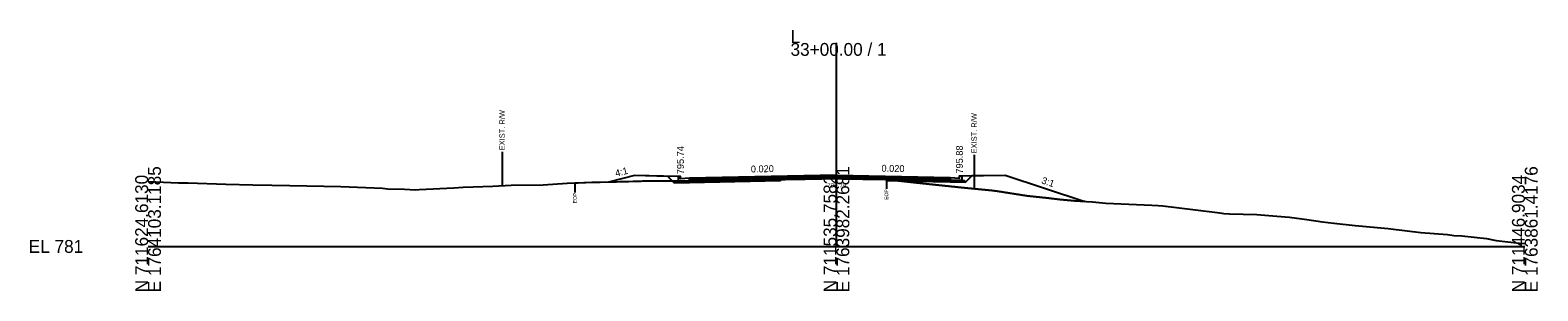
# Model space of a CAD drawing. Extents: x -26 to 5303, y -10 to 9578.
# Drawn here: x 1974.3 to 2302.8, y 2990.3 to 3047.2 of the extents above; entities that cross this region are included whole.
import ezdxf

# ---------------------------------------------------------------- set-up
doc = ezdxf.new("R2010")
doc.units = 0
for name, color, linetype in [('Default', 7, 'Continuous'), ('Exist CMT Pavement', 7, 'Continuous'), ('Exist Cross Section Cell', 7, 'Continuous'), ('Exist XS Ground Line', 7, 'Continuous'), ('Old_Level_10', 7, 'Continuous'), ('Old_Level_3', 7, 'Continuous'), ('Prop CMT Conc Surface', 7, 'Continuous'), ('Prop CMT Concrete Structures', 7, 'Continuous'), ('Prop CMT Pvmt Course 1', 7, 'Continuous'), ('Prop CMT Pvmt Course 1 CG', 7, 'Continuous'), ('Prop CMT Pvmt Course 2', 7, 'Continuous'), ('Prop CMT Pvmt Course 3', 7, 'Continuous'), ('Prop CMT Pvmt Surface', 7, 'Continuous'), ('Prop CMT Slope Grass', 7, 'Continuous'), ('Prop CMT Subgrade Earthwork', 7, 'Continuous'), ('Prop XS Earthwork Shape', 7, 'Continuous'), ('Prop XS Hydro Elevations', 7, 'Continuous'), ('Prop XS SE Text', 7, 'Continuous'), ('Prop XS Side Slope Text', 7, 'Continuous'), ('Prop XS Wedging', 7, 'Continuous')]:
    doc.layers.add(name, color=color, linetype=linetype)

msp = doc.modelspace()

# ---------------------------------------------------------------- linework, layer by layer
at = {"layer": 'Exist CMT Pavement'}
msp.add_lwpolyline([(2137.79, 3014.58), (2138.85, 3014.62), (2139.65, 3014.65), (2140.73, 3014.67), (2141.44, 3014.68), (2141.95, 3014.68), (2143.22, 3014.7), (2145.06, 3014.74), (2145.36, 3014.74), (2148.16, 3014.78), (2148.59, 3014.78), (2149.17, 3014.78), (2150, 3014.79), (2150.38, 3014.79), (2151.26, 3014.77), (2152.16, 3014.76), (2153.39, 3014.75), (2153.95, 3014.74), (2154.37, 3014.73), (2155.74, 3014.7), (2157.61, 3014.7), (2159.32, 3014.67), (2159.84, 3014.66), (2160.46, 3014.64), (2160.89, 3014.6), (2160.89, 3014.6)], dxfattribs=at)
at = {"layer": 'Exist Cross Section Cell'}
for p, q in [((2150, 3000), (2150, 3044.36)), ((2000, 3000), (2150, 3000)), ((2150, 3000), (2300, 3000))]:
    msp.add_line(p, q, dxfattribs=at)
at = {"layer": 'Exist XS Ground Line'}
msp.add_lwpolyline([(2000, 3014.14), (2001.72, 3014.08), (2006.62, 3013.86), (2007.68, 3013.84), (2008.73, 3013.83), (2016.98, 3013.61), (2022.82, 3013.46), (2027, 3013.38), (2030.88, 3013.25), (2041.99, 3013.03), (2051.11, 3012.67), (2052.18, 3012.54), (2055.88, 3012.49), (2058.27, 3012.37), (2059.1, 3012.44), (2066.61, 3012.79), (2068.69, 3012.95), (2075.13, 3013.14), (2079.13, 3013.35), (2086.12, 3013.41), (2091.34, 3013.76), (2093.02, 3013.84), (2093.73, 3013.86), (2094.94, 3013.92), (2095.41, 3013.94), (2096.73, 3014), (2098.53, 3014.03), (2100.31, 3014.08), (2101.62, 3014.09), (2102.09, 3014.1), (2102.75, 3014.12), (2103.88, 3014.16), (2104.72, 3014.18), (2105.67, 3014.22), (2106.97, 3014.25), (2107.46, 3014.26), (2107.82, 3014.27), (2109.25, 3014.29), (2111.19, 3014.32), (2112.82, 3014.29), (2114.03, 3014.31), (2114.61, 3014.32), (2115.41, 3014.31), (2116.4, 3014.31), (2117.13, 3014.31), (2118.19, 3014.33), (2119.63, 3014.34), (2120.23, 3014.34), (2121.76, 3014.35), (2123.85, 3014.35), (2126.44, 3014.41), (2127.13, 3014.42), (2128.07, 3014.43), (2129.54, 3014.44), (2130.71, 3014.45), (2132.29, 3014.46), (2132.65, 3014.47), (2133.64, 3014.49), (2135.75, 3014.55), (2136.51, 3014.56), (2137.86, 3014.58), (2138.85, 3014.62), (2139.65, 3014.65), (2140.73, 3014.67), (2141.44, 3014.68), (2141.95, 3014.68), (2143.22, 3014.7), (2145.06, 3014.74), (2146.8, 3014.77), (2148.16, 3014.78), (2148.59, 3014.78), (2149.17, 3014.78), (2150, 3014.79), (2150.38, 3014.79), (2151.26, 3014.77), (2152.16, 3014.76), (2153.39, 3014.75), (2154.37, 3014.73), (2157.08, 3014.7), (2157.61, 3014.7), (2159.32, 3014.67), (2159.84, 3014.66), (2160.46, 3014.64), (2160.89, 3014.6), (2167.42, 3013.86), (2177.19, 3012.86), (2183.87, 3012.18), (2185, 3012.05), (2191.5, 3011.05), (2196.29, 3010.53), (2198.66, 3010.24), (2201.88, 3009.91), (2205.81, 3009.72), (2208.7, 3009.41), (2218.76, 3008.98), (2220.12, 3008.92), (2221.11, 3008.87), (2227.64, 3008.04), (2233.53, 3007.29), (2234.43, 3007.2), (2235.65, 3007.13), (2241.58, 3006.99), (2245.94, 3006.61), (2248.73, 3006.39), (2252.53, 3005.87), (2255.89, 3005.37), (2258.36, 3005.04), (2263.04, 3004.58), (2269.41, 3003.97), (2270.19, 3003.89), (2270.77, 3003.83), (2277.35, 3003.03), (2283.18, 3002.57), (2284.5, 3002.35), (2286.3, 3002.29), (2291.66, 3001.7), (2293.77, 3001.32), (2298.81, 3000.74), (2300, 3000.66)], dxfattribs=at)
at = {"layer": 'Old_Level_10'}
for p, q in [((2077.13, 3020.64), (2077.13, 3013.24)), ((2180, 3019.98), (2180, 3012.58)), ((2093.02, 3013.84), (2093.02, 3011.79)), ((2160.89, 3014.6), (2160.89, 3012.55))]:
    msp.add_line(p, q, dxfattribs=at)
at = {"layer": 'Prop CMT Conc Surface'}
for points in [[(2116, 3014.74), (2116, 3015.24), (2115.5, 3015.24)], [(2118, 3014.86), (2116, 3014.74)], [(2174.8, 3015), (2176.8, 3014.88)], [(2176.8, 3014.88), (2176.8, 3015.38), (2177.3, 3015.38)]]:
    msp.add_lwpolyline(points, dxfattribs=at)
at = {"layer": 'Prop CMT Concrete Structures'}
for points in [[(2118, 3014.86), (2116, 3014.74), (2116, 3015.24), (2115.5, 3015.24)], [(2115.5, 3015.24), (2115.5, 3014.22), (2118, 3014.27)], [(2118, 3014.27), (2118, 3014.86)], [(2174.8, 3015), (2176.8, 3014.88), (2176.8, 3015.38), (2177.3, 3015.38)], [(2177.3, 3015.38), (2177.3, 3014.37), (2174.8, 3014.42)], [(2174.8, 3014.42), (2174.8, 3015)]]:
    msp.add_lwpolyline(points, dxfattribs=at)
at = {"layer": 'Prop CMT Pvmt Course 1'}
for points in [[(2150, 3015.5), (2118, 3014.86)], [(2118, 3014.61), (2137.79, 3015)], [(2118, 3014.86), (2118, 3014.61)], [(2137.79, 3015), (2150, 3015.25)], [(2137.79, 3015), (2137.79, 3015)], [(2150, 3015.25), (2150, 3015.5)], [(2150, 3015.5), (2174.8, 3015)], [(2150, 3015.25), (2150, 3015.25), (2150, 3015.25)], [(2160.89, 3015.03), (2150, 3015.25)], [(2174.8, 3014.75), (2160.89, 3015.03)], [(2160.89, 3015.03), (2160.89, 3015.03)], [(2174.8, 3015), (2174.8, 3014.75)]]:
    msp.add_lwpolyline(points, dxfattribs=at)
at = {"layer": 'Prop CMT Pvmt Course 1 CG'}
for points in [[(2118, 3014.27), (2115, 3014.21), (2114.66, 3013.87)], [(2114.66, 3013.87), (2118, 3013.94)], [(2118, 3013.94), (2118, 3014.27)], [(2174.8, 3014.42), (2177.8, 3014.36), (2178.14, 3014.02)], [(2174.8, 3014.08), (2174.8, 3014.42)], [(2178.14, 3014.02), (2174.8, 3014.08)]]:
    msp.add_lwpolyline(points, dxfattribs=at)
at = {"layer": 'Prop CMT Pvmt Course 2'}
for points in [[(2137.79, 3015), (2118, 3014.61)], [(2118, 3014.27), (2137.79, 3014.67)], [(2118, 3014.61), (2118, 3014.27)], [(2137.79, 3014.67), (2137.79, 3015)], [(2160.89, 3014.7), (2160.89, 3015.03)], [(2160.89, 3015.03), (2174.8, 3014.75)], [(2174.8, 3014.42), (2160.89, 3014.7)], [(2174.8, 3014.75), (2174.8, 3014.42)]]:
    msp.add_lwpolyline(points, dxfattribs=at)
at = {"layer": 'Prop CMT Pvmt Course 3'}
for points in [[(2137.79, 3014.67), (2118, 3014.27)], [(2118, 3013.94), (2137.79, 3014.34)], [(2118, 3014.27), (2118, 3013.94)], [(2137.79, 3014.34), (2137.79, 3014.67)], [(2160.89, 3014.7), (2174.8, 3014.42)], [(2160.89, 3014.36), (2160.89, 3014.7)], [(2174.8, 3014.08), (2160.89, 3014.36)], [(2174.8, 3014.42), (2174.8, 3014.08)]]:
    msp.add_lwpolyline(points, dxfattribs=at)
at = {"layer": 'Prop CMT Pvmt Surface'}
for points in [[(2150, 3015.5), (2118, 3014.86)], [(2150, 3015.5), (2174.8, 3015)]]:
    msp.add_lwpolyline(points, dxfattribs=at)
at = {"layer": 'Prop CMT Slope Grass'}
for points in [[(2115.5, 3015.24), (2106, 3015.43), (2100.62, 3014.08)], [(2177.3, 3015.38), (2186.8, 3015.57), (2204.1, 3009.81)]]:
    msp.add_lwpolyline(points, dxfattribs=at)
at = {"layer": 'Prop CMT Subgrade Earthwork'}
for p, q in [((2137.79, 3014.34), (2137.79, 3014.58)), ((2160.89, 3014.36), (2160.89, 3014.6))]:
    msp.add_line(p, q, dxfattribs=at)
for points in [[(2118, 3013.94), (2114.66, 3013.87), (2113.25, 3015.28)], [(2137.79, 3014.34), (2118, 3013.94)], [(2160.89, 3014.36), (2174.8, 3014.08)], [(2174.8, 3014.08), (2178.14, 3014.02), (2179.55, 3015.43)]]:
    msp.add_lwpolyline(points, dxfattribs=at)
at = {"layer": 'Prop XS Earthwork Shape'}
for points in [[(2101.62, 3014.09), (2102.09, 3014.1), (2102.75, 3014.12), (2103.88, 3014.16), (2104.72, 3014.18), (2105.67, 3014.22), (2106.97, 3014.25), (2107.46, 3014.26), (2107.82, 3014.27), (2109.25, 3014.29), (2111.19, 3014.32), (2112.82, 3014.29), (2114.03, 3014.31), (2114.22, 3014.31), (2113.25, 3015.28), (2106, 3015.43), (2100.62, 3014.08)], [(2107.46, 3014.26), (2107.82, 3014.27), (2109.25, 3014.29), (2111.19, 3014.32), (2112.82, 3014.29), (2114.03, 3014.31), (2114.22, 3014.31), (2113.25, 3015.28), (2106, 3015.43), (2100.62, 3014.08), (2101.62, 3014.09), (2102.09, 3014.1), (2102.75, 3014.12), (2103.88, 3014.16), (2104.72, 3014.18), (2105.67, 3014.22), (2106.97, 3014.25)], [(2137.79, 3014.34), (2118, 3013.94), (2114.66, 3013.87), (2114.22, 3014.31), (2114.61, 3014.32), (2115.41, 3014.31), (2116.4, 3014.31), (2117.13, 3014.31), (2118.19, 3014.33), (2119.63, 3014.34), (2120.23, 3014.34), (2121.76, 3014.35), (2123.85, 3014.35), (2125.34, 3014.38), (2126.44, 3014.41), (2127.13, 3014.42), (2128.07, 3014.43), (2128.92, 3014.44), (2129.54, 3014.44), (2132.65, 3014.47), (2134.28, 3014.5), (2135.75, 3014.55), (2136.07, 3014.55), (2136.51, 3014.56), (2137.79, 3014.58)], [(2121.76, 3014.35), (2123.85, 3014.35), (2125.34, 3014.38), (2126.44, 3014.41), (2127.13, 3014.42), (2128.07, 3014.43), (2128.92, 3014.44), (2129.54, 3014.44), (2132.65, 3014.47), (2134.28, 3014.5), (2135.75, 3014.55), (2136.07, 3014.55), (2136.51, 3014.56), (2137.79, 3014.58), (2137.79, 3014.34), (2118, 3013.94), (2114.66, 3013.87), (2114.22, 3014.31), (2114.61, 3014.32), (2115.41, 3014.31), (2116.4, 3014.31), (2117.13, 3014.31), (2118.19, 3014.33), (2119.63, 3014.34), (2120.23, 3014.34)], [(2160.89, 3014.36), (2163.44, 3014.31), (2160.89, 3014.6)], [(2174.8, 3014.08), (2178.14, 3014.02), (2179.55, 3015.43), (2186.8, 3015.57), (2204.1, 3009.81), (2201.88, 3009.91), (2198.66, 3010.24), (2196.29, 3010.53), (2191.5, 3011.05), (2185, 3012.05), (2183.87, 3012.18), (2177.19, 3012.86), (2167.42, 3013.86), (2163.44, 3014.31)], [(2186.8, 3015.57), (2204.1, 3009.81), (2201.88, 3009.91), (2198.66, 3010.24), (2196.29, 3010.53), (2191.5, 3011.05), (2185, 3012.05), (2183.87, 3012.18), (2177.19, 3012.86), (2167.42, 3013.86), (2163.44, 3014.31), (2174.8, 3014.08), (2178.14, 3014.02), (2179.55, 3015.43)]]:
    msp.add_lwpolyline(points, close=True, dxfattribs=at)
at = {"layer": 'Prop XS Wedging'}
msp.add_lwpolyline([(2137.86, 3014.58), (2137.86, 3015), (2138.85, 3015.02), (2139.65, 3015.04), (2140.73, 3015.06), (2141.43, 3015.08), (2141.95, 3015.09), (2143.22, 3015.11), (2145.06, 3015.15), (2145.36, 3015.15), (2148.16, 3015.21), (2148.59, 3015.22), (2149.17, 3015.23), (2150, 3015.25), (2150.38, 3015.24), (2151.26, 3015.22), (2152.16, 3015.2), (2153.39, 3015.18), (2153.95, 3015.17), (2154.37, 3015.16), (2155.74, 3015.13), (2157.61, 3015.09), (2159.32, 3015.06), (2159.84, 3015.05), (2160.46, 3015.04), (2160.89, 3015.03), (2160.89, 3014.6), (2160.46, 3014.64), (2159.84, 3014.66), (2159.32, 3014.67), (2157.61, 3014.7), (2155.74, 3014.7), (2154.37, 3014.73), (2153.95, 3014.74), (2153.39, 3014.75), (2152.16, 3014.76), (2151.26, 3014.77), (2150.38, 3014.79), (2150, 3014.79), (2149.17, 3014.78), (2148.59, 3014.78), (2148.16, 3014.78), (2145.36, 3014.74), (2145.06, 3014.74), (2143.22, 3014.7), (2141.95, 3014.68), (2141.43, 3014.68), (2140.73, 3014.67), (2139.65, 3014.65), (2138.85, 3014.62)], close=True, dxfattribs=at)

# ---------------------------------------------------------------- texts
at = {"layer": 'Default'}
msp.add_text('-', height=0.0001, dxfattribs=at).set_placement((2000, 3000))
at = {"layer": 'Exist Cross Section Cell'}
for s, p in [('L', (2140, 3044.36)), ('33+00.00 / 1', (2140, 3041.56)), ('EL 781', (1974, 2998.6))]:
    msp.add_text(s, height=2.8, dxfattribs=at).set_placement(p)
for s, p in [('E 1764103.1185', (2002.8, 2990)), ('E 1763982.2681', (2152.8, 2990)), ('E 1763861.4176', (2302.8, 2990)), ('N 711624.6130', (2000, 2990)), ('N 711535.7582', (2150, 2990)), ('N 711446.9034', (2300, 2990))]:
    msp.add_text(s, height=2.8, rotation=90, dxfattribs=at).set_placement(p)
at = {"layer": 'Old_Level_10'}
for s, height, p in [('EXIST. R/W', 1.181, (2077.73, 3020.95)), ('EXIST. R/W', 1.181, (2180.59, 3020.28)), ('EOP', 0.787, (2093.41, 3009.39)), ('EOP', 0.787, (2161.28, 3010.15))]:
    msp.add_text(s, height=height, rotation=90, dxfattribs=at).set_placement(p)
at = {"layer": 'Old_Level_3'}
msp.add_text('795.79', height=1, dxfattribs=at).set_placement((2147.95, 3012.79))
at = {"layer": 'Prop XS Hydro Elevations'}
for s, p in [('795.74', (2116.75, 3015.74)), ('795.88', (2177.55, 3015.88))]:
    msp.add_text(s, height=1.5, rotation=90, dxfattribs=at).set_placement(p)
at = {"layer": 'Prop XS SE Text'}
for rotation, p in [(1.1458, (2131.36, 3016.12)), (358.8542, (2159.8, 3016.3))]:
    msp.add_text('0.020', height=1.5, rotation=rotation, dxfattribs=at).set_placement(p)
at = {"layer": 'Prop XS Side Slope Text'}
for s, rotation, p in [('4:1', 14.0362, (2101.98, 3015.19)), ('3:1', 341.5651, (2194.56, 3013.78))]:
    msp.add_text(s, height=1.5, rotation=rotation, dxfattribs=at).set_placement(p)

doc.saveas('drawing.dxf')
